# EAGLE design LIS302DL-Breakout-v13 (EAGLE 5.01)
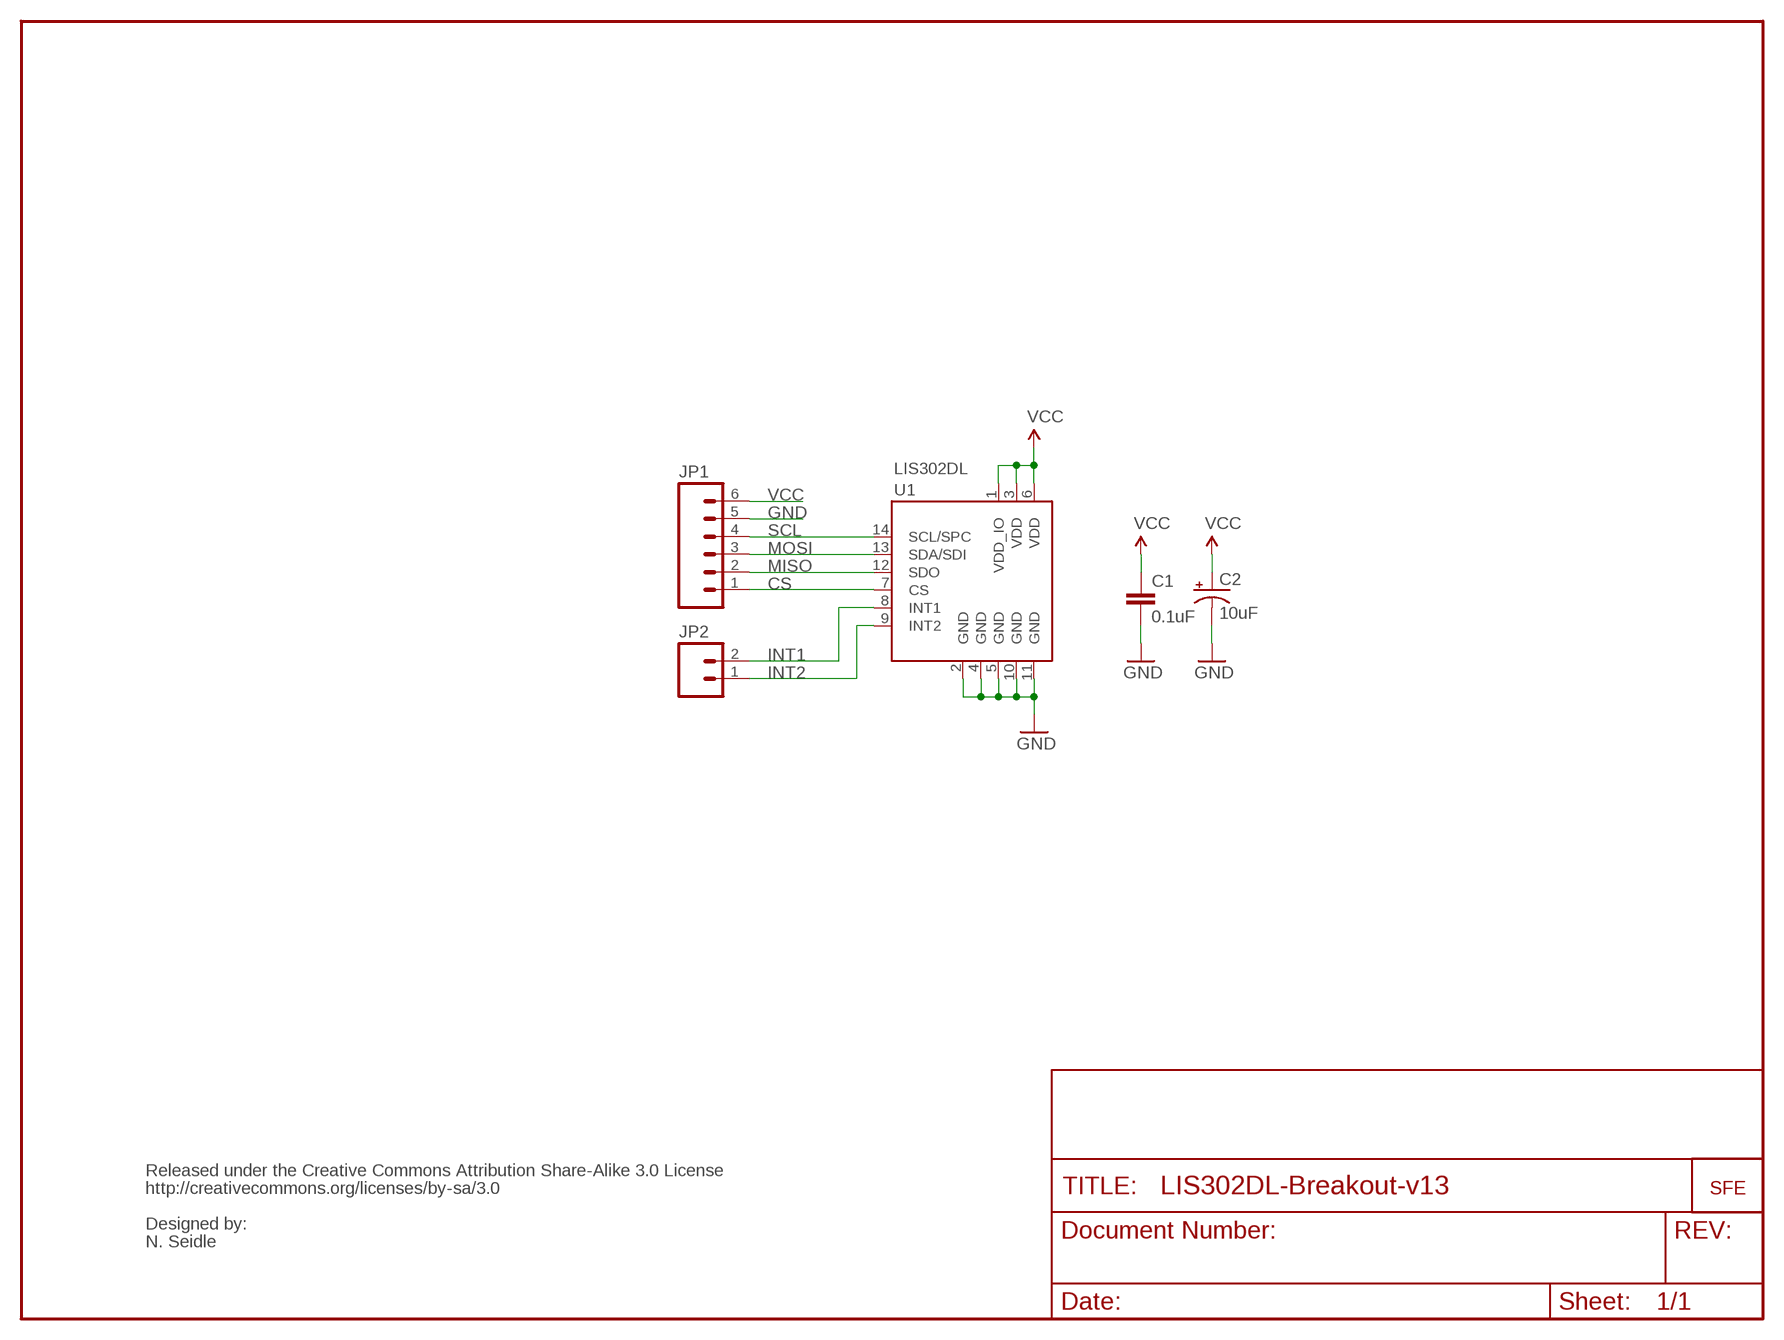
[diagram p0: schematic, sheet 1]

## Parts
C1  0.1uF  CAP0402  [C0402]
C2  10uF  CAP_POL1206  [EIA3216]
JP1  M06SIP  [1X06]
JP2  M02PTH  [1X02]
U1  LIS302DL  [LGA14]
U$1  LOGO-SFESK  [SFE-LOGO-FLAME]

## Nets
CS: JP1.1 U1.7(CS)
GND: C1.2 C2.C(-) JP1.5 U1.2(GND) U1.4(GND) U1.5(GND) U1.10(GND) U1.11(GND)
INT1: JP2.2 U1.8(INT1)
INT2: JP2.1 U1.9(INT2)
MISO: JP1.2 U1.12(SDO)
MOSI: JP1.3 U1.13(SDA/SDI)
SCL: JP1.4 U1.14(SCL/SPC)
VCC: C1.1 C2.A(+) JP1.6 U1.1(VDD_IO) U1.3(VDD) U1.6(VDD)

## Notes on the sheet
- Released under the Creative Commons Attribution Share-Alike 3.0 License
- http://creativecommons.org/licenses/by-sa/3.0
- Designed by:
- N. Seidle

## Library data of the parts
C1 = SparkFun:CAP: Capacitor
C2 = SparkFun:CAP_POL: Capacitor Polarized
JP1 = SparkFun:M06: Header 6 Standard 6-pin 0.1" header. Use with straight break away headers (SKU : PRT-00116), right angle break away headers (PRT-00553), swiss pins (PRT-00743), machine pins (PRT-00117), and female headers (PRT-00115). Molex polarized connector foot print use with SKU : PRT-08094 with associated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
JP2 = SparkFun:M02: Header 2
U1 = SparkFun:LIS302DL
U$1 = SparkFun:LOGO-SFE: Spark Fun Electronics PCB Logo

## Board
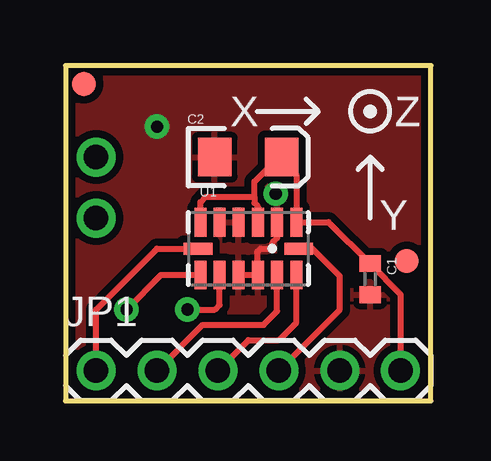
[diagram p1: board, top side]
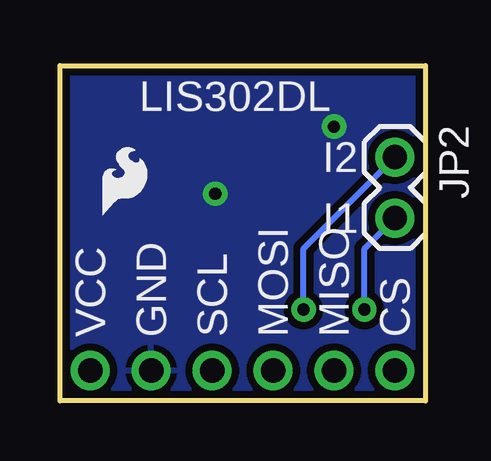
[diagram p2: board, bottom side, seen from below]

Size 15.24 x 13.97 mm. Coordinates in mm from the lower left corner, seen from the top.
Outline: 0,0 15.24,0 15.24,13.97 0,13.97 0,0
Copper layers (1*16): Top 0.035mm / dielectric 1.5mm / Bottom 0.035mm
Design rules "SparkFun": minimum track width 8mil, minimum drill 20mil, track to track 8mil, track to pad 8mil, pad to pad 8mil, via to via 8mil, smd to smd 8mil, copper to edge 10mil, drill to drill 8mil, minimum pad ring 12mil, minimum via ring 10mil, stop-mask expansion 4mil, vias tented up to drill 20mil, thermal gap 10mil

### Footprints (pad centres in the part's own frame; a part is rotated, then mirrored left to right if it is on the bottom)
C0402 = smd 0.7 x 0.9: 1 -0.65,0; 2 0.65,0
EIA3216 = smd 1.4 x 1.6: A 1.4,0; C -1.4,0
FIDUCIAL-1X2 = smd 1 x 1: 1 0,0
1X06 = drill 1.016 round: 1 0,0; 2 2.54,0; 3 5.08,0; 4 7.62,0; 5 10.16,0; 6 12.7,0
1X02 = drill 1.016 round: 1 0,0; 2 2.54,0
LGA14 = smd 0.5 x 1.2: 1 2,1.1; 2 1.2,1.1; 3 0.4,1.1; 4 -0.4,1.1; 5 -1.2,1.1; 6 -2,1.1; 8 -2,-1.1; 9 -1.2,-1.1; 10 -0.4,-1.1; 11 0.4,-1.1; 12 1.2,-1.1; 13 2,-1.1 | smd 1.2 x 0.5: 7 -2.1,0; 14 2.1,0

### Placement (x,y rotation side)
C1  12.7,5.08 270 top
C2  7.62,10.16 0 top
E$1  [FIDUCIAL-1X2]  0.76,13.21 0 top
E$2  [FIDUCIAL-1X2]  14.22,5.84 0 top
JP1  1.27,1.27 0 top
JP2  1.27,10.16 270 bottom
U1  7.62,6.35 0 top
U$1  13.46,7.75 0 bottom

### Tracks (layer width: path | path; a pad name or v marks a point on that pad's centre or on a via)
CS
  Top 0.254: U1.7 3.81,6.35 1.27,3.81 1.27,1.4 1.4,1.27 JP1.1
GND  (via drill 0.51)
  Top 0.254: U1.10 7.22,5.23 7.24,5.21 7.28,5.25 U1.11 8.02,5.32 8,5.33 8,6.22 8.13,6.35 8.51,6.35 8.64,6.48 8.64,6.6 8.82,6.79 U1.2
  other vias: 8.76,8.64 3.81,11.43
  pour Bottom (isolate 0.305): 0,0 0,13.97 15.24,13.97 15.24,0
  pour Top (isolate 0.305): 0,0 0,13.97 15.24,13.97 15.24,0
INT1  (via drill 0.51)
  Top 0.254: U1.8 3.98,5.25 v2.54,3.81
  Bottom 0.254: v2.54,3.81 2.54,6.35 JP2.2
INT2  (via drill 0.51)
  Top 0.254: U1.9 6.42,4.01 6.22,3.81 v5.08,3.81
  Bottom 0.254: v5.08,3.81 5.08,6.35 JP2.1
MISO
  Top 0.254: U1.12 8.82,3.74 8.26,3.17 5.71,3.17 JP1.2
MOSI
  Top 0.254: U1.13 9.62,3.27 8.89,2.54 7.62,2.54 JP1.3
SCL
  Top 0.254: U1.14 10.29,6.35 11.43,5.21 11.43,3.81 JP1.4
VCC
  Top 0.254: 8.89,10.16 9.62,9.43 U1.1 10.96,7.45 12.7,5.71 | 8.89,10.16 C2.A | U1.6 5.62,8.29 5.84,8.51 7.87,8.51 | 12.7,5.71 C1.1 | JP1.6 13.97,4.45 12.7,5.71 | 8.89,10.16 7.87,9.14 7.87,8.51 | 7.87,8.51 7.87,8.26 8.02,8.11 U1.3

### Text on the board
tPlace: N. Seidle | X | Z | Y | Released under the Creative Commons Attribution Share-Alike 3.0 License | http://creativecommons.org/licenses/by-sa/3.0
bPlace: LIS302DL | I2 | I1 | CS | MISO | MOSI | SCL | GND | VCC
tValues: DNP | DNP | LIS302DL Breakout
